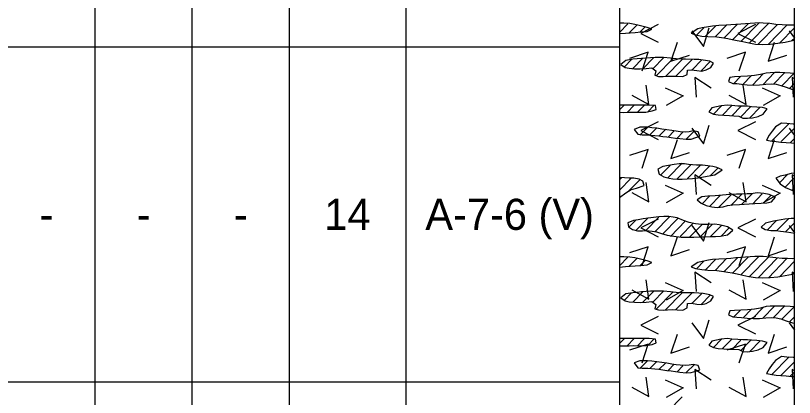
# Model space of a CAD drawing. Extents: x -0.01 to 0.83, y -0.63 to 1.27.
# Drawn here: x 0.6664 to 0.8333, y 0.7859 to 0.8677 of the extents above; entities that cross this region are included whole.
import ezdxf

# ---------------------------------------------------------------- set-up
doc = ezdxf.new("R2010")
doc.units = 0

msp = doc.modelspace()

# ---------------------------------------------------------------- linework, layer by layer
for points in [[(0, 0), (0.83333, 0), (0.83333, 1.275), (0, 1.275)], [(0, 0), (0.83333, 0), (0.83333, 1.275), (0, 1.275)], [(0, 0), (0.83333, 0), (0.83333, 1.275), (0, 1.275)], [(0, 0), (0.83333, 0), (0.83333, 1.275), (0, 1.275)], [(0, 0), (0.83333, 0), (0.83333, 1.275), (0, 1.275)], [(0.79583, 0.86382), (0.79715, 0.86393), (0.79814, 0.86401), (0.79922, 0.86408), (0.80039, 0.86417), (0.80179, 0.86429), (0.80275, 0.8648), (0.80179, 0.86515), (0.80091, 0.86536), (0.80003, 0.86558), (0.79909, 0.86579), (0.79803, 0.86595), (0.79677, 0.86605), (0.79583, 0.86603)], [(0.82816, 0.86157), (0.82978, 0.86174), (0.83137, 0.862), (0.8329, 0.86231), (0.83333, 0.86241), (0.83333, 0.86565), (0.83295, 0.86562), (0.83188, 0.86564), (0.83071, 0.86569), (0.82938, 0.8658), (0.82807, 0.86597), (0.82662, 0.86608), (0.82576, 0.86609), (0.82484, 0.86606), (0.82387, 0.86601), (0.82286, 0.86594), (0.82182, 0.86586), (0.82077, 0.86578), (0.81973, 0.86569), (0.81872, 0.86562), (0.81715, 0.86552), (0.81579, 0.86543), (0.81491, 0.8653), (0.81357, 0.86502), (0.8126, 0.86481), (0.81121, 0.86389), (0.8121, 0.86353), (0.81345, 0.86328), (0.81479, 0.86319), (0.81668, 0.86309), (0.81818, 0.86289), (0.81905, 0.86274), (0.82, 0.86257), (0.82107, 0.86235), (0.82225, 0.8621), (0.82357, 0.86181), (0.82501, 0.86158), (0.82656, 0.86151)], [(0.79708, 0.85659), (0.79794, 0.85641), (0.79904, 0.8563), (0.80028, 0.85627), (0.80156, 0.85632), (0.80274, 0.85648), (0.80361, 0.85582), (0.80338, 0.85492), (0.80422, 0.85465), (0.80517, 0.85463), (0.80613, 0.85469), (0.8072, 0.85472), (0.80818, 0.85469), (0.80939, 0.85461), (0.81037, 0.85508), (0.81038, 0.85602), (0.8113, 0.85609), (0.81244, 0.8559), (0.81346, 0.85579), (0.81438, 0.85605), (0.81539, 0.85659), (0.81601, 0.8575), (0.81517, 0.85788), (0.81374, 0.85815), (0.81285, 0.85825), (0.81187, 0.8583), (0.81, 0.85831), (0.8091, 0.85832), (0.808, 0.8584), (0.80678, 0.85856), (0.8053, 0.85869), (0.80443, 0.8587), (0.80349, 0.85868), (0.80251, 0.85864), (0.80152, 0.85858), (0.80054, 0.8585), (0.79959, 0.85841), (0.7987, 0.85831), (0.79722, 0.85809), (0.79614, 0.85721)], [(0.83241, 0.85537), (0.83129, 0.85544), (0.83017, 0.85547), (0.8291, 0.85548), (0.82811, 0.85544), (0.82728, 0.85535), (0.82608, 0.85505), (0.82476, 0.85482), (0.8233, 0.85469), (0.82183, 0.85461), (0.82051, 0.85455), (0.81951, 0.85445), (0.81922, 0.85358), (0.82013, 0.85316), (0.82097, 0.85311), (0.822, 0.85301), (0.82318, 0.85288), (0.82448, 0.85279), (0.82584, 0.85282), (0.82719, 0.85298), (0.82836, 0.85305), (0.8294, 0.85297), (0.83043, 0.85274), (0.83156, 0.85235), (0.83291, 0.85186), (0.83333, 0.85178), (0.83333, 0.8553)], [(0.79583, 0.84696), (0.79676, 0.84695), (0.79792, 0.84697), (0.79882, 0.84701), (0.79992, 0.84697), (0.80151, 0.84701), (0.80282, 0.84727), (0.80367, 0.84759), (0.80354, 0.84842), (0.80216, 0.84851), (0.79583, 0.84851)], [(0.81822, 0.84632), (0.81944, 0.84626), (0.82033, 0.84622), (0.82145, 0.84615), (0.82229, 0.84573), (0.82324, 0.84569), (0.82438, 0.8458), (0.82555, 0.84608), (0.82662, 0.84659), (0.82749, 0.84769), (0.82651, 0.84799), (0.82524, 0.84809), (0.82413, 0.84815), (0.82324, 0.84826), (0.82226, 0.84828), (0.82121, 0.8483), (0.81995, 0.84839), (0.81902, 0.84851), (0.81761, 0.84837), (0.81566, 0.84793), (0.81496, 0.84709), (0.81598, 0.8466), (0.81695, 0.84642)], [(0.80066, 0.84216), (0.80188, 0.84215), (0.80339, 0.84202), (0.80423, 0.84193), (0.8051, 0.84182), (0.806, 0.8417), (0.80692, 0.84158), (0.80784, 0.84146), (0.80875, 0.84135), (0.81014, 0.84121), (0.81119, 0.84122), (0.81222, 0.84157), (0.81308, 0.84185), (0.81267, 0.84275), (0.8116, 0.843), (0.81075, 0.8428), (0.80989, 0.84272), (0.80885, 0.8428), (0.80799, 0.84291), (0.80703, 0.84306), (0.806, 0.84322), (0.80492, 0.84339), (0.80384, 0.84354), (0.8028, 0.84367), (0.80182, 0.84377), (0.8002, 0.84378), (0.79901, 0.8433), (0.79974, 0.84226)], [(0.83305, 0.84446), (0.83171, 0.84457), (0.83054, 0.84467), (0.82925, 0.84385), (0.82857, 0.84294), (0.82792, 0.84205), (0.82735, 0.84103), (0.82858, 0.8408), (0.82945, 0.8407), (0.83045, 0.8406), (0.83155, 0.84051), (0.83272, 0.84041), (0.83333, 0.84036), (0.83333, 0.84445)], [(0.81233, 0.83565), (0.81063, 0.83577), (0.80977, 0.83591), (0.8086, 0.83591), (0.80755, 0.83577), (0.80632, 0.83557), (0.80513, 0.83533), (0.80403, 0.83481), (0.80436, 0.83374), (0.80536, 0.83318), (0.80647, 0.83288), (0.8073, 0.83273), (0.80824, 0.83265), (0.80926, 0.83264), (0.81035, 0.83269), (0.81149, 0.8328), (0.81267, 0.83294), (0.81386, 0.83313), (0.81506, 0.83334), (0.81625, 0.83357), (0.81783, 0.83466), (0.81673, 0.83515), (0.81585, 0.83536), (0.8148, 0.83551), (0.81361, 0.83562)], [(0.83265, 0.83384), (0.83136, 0.83353), (0.83028, 0.83326), (0.82934, 0.83286), (0.83026, 0.83166), (0.83142, 0.8309), (0.83279, 0.83032), (0.83333, 0.83022), (0.83333, 0.83393)], [(0.79583, 0.82874), (0.79719, 0.82973), (0.79831, 0.83044), (0.79951, 0.83071), (0.80111, 0.83131), (0.80086, 0.83219), (0.80002, 0.83267), (0.79889, 0.83286), (0.79791, 0.83289), (0.79694, 0.83295), (0.79583, 0.83303)], [(0.82537, 0.82969), (0.82408, 0.82954), (0.82319, 0.82948), (0.82214, 0.82946), (0.82091, 0.82942), (0.81947, 0.82933), (0.81792, 0.82921), (0.81632, 0.82909), (0.81475, 0.82899), (0.81348, 0.82889), (0.81247, 0.82825), (0.81337, 0.82749), (0.81444, 0.82699), (0.81561, 0.8267), (0.81675, 0.8266), (0.81807, 0.82671), (0.81896, 0.82698), (0.82003, 0.82713), (0.82157, 0.82725), (0.82253, 0.82731), (0.82362, 0.82737), (0.82483, 0.82743), (0.82618, 0.82749), (0.82745, 0.8276), (0.82842, 0.82778), (0.82927, 0.82883), (0.82791, 0.82935), (0.82679, 0.82955)], [(0.79885, 0.82378), (0.79763, 0.82332), (0.79773, 0.82242), (0.79859, 0.8219), (0.7997, 0.8216), (0.80074, 0.82161), (0.80165, 0.82163), (0.80281, 0.82154), (0.80377, 0.82134), (0.80486, 0.82099), (0.80606, 0.82069), (0.80751, 0.82042), (0.80905, 0.82023), (0.81052, 0.8202), (0.81177, 0.82026), (0.81289, 0.8203), (0.81408, 0.82033), (0.81553, 0.82037), (0.81642, 0.8204), (0.81745, 0.82043), (0.81897, 0.8207), (0.82011, 0.82174), (0.81896, 0.82241), (0.8181, 0.82268), (0.81717, 0.82287), (0.81626, 0.82298), (0.81479, 0.82292), (0.81343, 0.82292), (0.8121, 0.82307), (0.8108, 0.82337), (0.80953, 0.82383), (0.8082, 0.82438), (0.80736, 0.82454), (0.8064, 0.82462), (0.80536, 0.82462), (0.80427, 0.82456), (0.80314, 0.82445), (0.80201, 0.8243), (0.8009, 0.82414), (0.79984, 0.82396)], [(0.83263, 0.82423), (0.83126, 0.82409), (0.82969, 0.82382), (0.82883, 0.82365), (0.82712, 0.82324), (0.82623, 0.82237), (0.82708, 0.82188), (0.82831, 0.82169), (0.82941, 0.82163), (0.83033, 0.82154), (0.83165, 0.82135), (0.83253, 0.82121), (0.83333, 0.82107), (0.83333, 0.82422)], [(0.79583, 0.81382), (0.79715, 0.81393), (0.79814, 0.81401), (0.79922, 0.81408), (0.80039, 0.81417), (0.80179, 0.81429), (0.80275, 0.8148), (0.80179, 0.81515), (0.80091, 0.81536), (0.80003, 0.81558), (0.79909, 0.81579), (0.79803, 0.81595), (0.79677, 0.81605), (0.79583, 0.81603)], [(0.82816, 0.81157), (0.82978, 0.81174), (0.83137, 0.812), (0.8329, 0.81231), (0.83333, 0.81241), (0.83333, 0.81565), (0.83295, 0.81562), (0.83188, 0.81564), (0.83071, 0.81569), (0.82938, 0.8158), (0.82807, 0.81597), (0.82662, 0.81608), (0.82576, 0.81609), (0.82484, 0.81606), (0.82387, 0.81601), (0.82286, 0.81594), (0.82182, 0.81586), (0.82077, 0.81578), (0.81973, 0.81569), (0.81872, 0.81562), (0.81715, 0.81552), (0.81579, 0.81543), (0.81491, 0.8153), (0.81357, 0.81502), (0.8126, 0.81481), (0.81121, 0.81389), (0.8121, 0.81353), (0.81345, 0.81328), (0.81479, 0.81319), (0.81668, 0.81309), (0.81818, 0.81289), (0.81905, 0.81274), (0.82, 0.81257), (0.82107, 0.81235), (0.82225, 0.8121), (0.82357, 0.81181), (0.82501, 0.81158), (0.82656, 0.81151)], [(0.79708, 0.80659), (0.79794, 0.80641), (0.79904, 0.8063), (0.80028, 0.80627), (0.80156, 0.80632), (0.80274, 0.80648), (0.80361, 0.80582), (0.80338, 0.80492), (0.80422, 0.80465), (0.80517, 0.80463), (0.80613, 0.80469), (0.8072, 0.80472), (0.80818, 0.80469), (0.80939, 0.80461), (0.81037, 0.80508), (0.81038, 0.80602), (0.8113, 0.80609), (0.81244, 0.8059), (0.81346, 0.80579), (0.81438, 0.80605), (0.81539, 0.80659), (0.81601, 0.8075), (0.81517, 0.80788), (0.81374, 0.80815), (0.81285, 0.80825), (0.81187, 0.8083), (0.81, 0.80831), (0.8091, 0.80832), (0.808, 0.8084), (0.80678, 0.80856), (0.8053, 0.80869), (0.80443, 0.8087), (0.80349, 0.80868), (0.80251, 0.80864), (0.80152, 0.80858), (0.80054, 0.8085), (0.79959, 0.80841), (0.7987, 0.80831), (0.79722, 0.80809), (0.79614, 0.80721)], [(0.83241, 0.80537), (0.83129, 0.80544), (0.83017, 0.80548), (0.8291, 0.80548), (0.82811, 0.80544), (0.82728, 0.80535), (0.82608, 0.80505), (0.82476, 0.80482), (0.8233, 0.80469), (0.82183, 0.80461), (0.82051, 0.80455), (0.81951, 0.80445), (0.81922, 0.80358), (0.82013, 0.80316), (0.82097, 0.80311), (0.822, 0.80301), (0.82318, 0.80288), (0.82448, 0.80279), (0.82584, 0.80282), (0.82719, 0.80298), (0.82836, 0.80305), (0.8294, 0.80297), (0.83043, 0.80274), (0.83156, 0.80235), (0.83291, 0.80186), (0.83333, 0.80178), (0.83333, 0.8053)], [(0.79583, 0.79696), (0.79676, 0.79695), (0.79792, 0.79697), (0.79882, 0.79701), (0.79992, 0.79697), (0.80151, 0.79701), (0.80282, 0.79727), (0.80367, 0.79759), (0.80354, 0.79842), (0.80216, 0.79851), (0.79583, 0.79851)], [(0.81822, 0.79632), (0.81944, 0.79626), (0.82033, 0.79622), (0.82145, 0.79615), (0.82229, 0.79574), (0.82324, 0.79569), (0.82438, 0.7958), (0.82555, 0.79608), (0.82662, 0.79659), (0.82749, 0.79769), (0.82651, 0.79799), (0.82524, 0.79809), (0.82413, 0.79815), (0.82324, 0.79826), (0.82226, 0.79828), (0.82121, 0.7983), (0.81995, 0.79839), (0.81902, 0.79851), (0.81761, 0.79837), (0.81566, 0.79793), (0.81496, 0.79709), (0.81598, 0.7966), (0.81695, 0.79642)], [(0.80066, 0.79216), (0.80188, 0.79215), (0.80339, 0.79202), (0.80423, 0.79193), (0.8051, 0.79182), (0.806, 0.7917), (0.80692, 0.79158), (0.80784, 0.79146), (0.80875, 0.79135), (0.81014, 0.79121), (0.81119, 0.79122), (0.81222, 0.79157), (0.81308, 0.79185), (0.81267, 0.79275), (0.8116, 0.793), (0.81075, 0.7928), (0.80989, 0.79272), (0.80885, 0.7928), (0.80799, 0.79291), (0.80703, 0.79306), (0.806, 0.79322), (0.80492, 0.79339), (0.80384, 0.79354), (0.8028, 0.79367), (0.80182, 0.79377), (0.8002, 0.79378), (0.79901, 0.7933), (0.79974, 0.79226)], [(0.83305, 0.79446), (0.83171, 0.79457), (0.83054, 0.79467), (0.82925, 0.79385), (0.82857, 0.79294), (0.82792, 0.79205), (0.82735, 0.79103), (0.82858, 0.7908), (0.82945, 0.7907), (0.83045, 0.7906), (0.83155, 0.79051), (0.83272, 0.79041), (0.83333, 0.79036), (0.83333, 0.79445)]]:
    msp.add_lwpolyline(points, close=True)
for points in [[(0.725, 1.22083), (0.725, -0.62183)], [(0.75, 1.22083), (0.75, -0.62183)], [(0.75, 1.22083), (0.75, -0.62183)], [(0.79583, 1.22083), (0.79583, -0.62183)], [(0.68333, 1.20833), (0.68333, -0.62183)], [(0.70417, 1.20833), (0.70417, -0.62183)], [(0.725, 1.20833), (0.725, -0.62183)], [(0.83333, -0.62183), (0.83333, 1.13843)], [(0.79765, 0.86594), (0.79583, 0.86407)], [(0.7996, 0.86572), (0.79786, 0.86394)], [(0.8013, 0.86524), (0.80027, 0.86419)], [(0.80412, 0.86575), (0.80038, 0.86387), (0.80412, 0.862)], [(0.81134, 0.86441), (0.81384, 0.86103), (0.81503, 0.86503)], [(0.81392, 0.86508), (0.81235, 0.86348)], [(0.8143, 0.86326), (0.8165, 0.86551)], [(0.8164, 0.86319), (0.81879, 0.86564)], [(0.81829, 0.86291), (0.82114, 0.86584)], [(0.82004, 0.86249), (0.82346, 0.866)], [(0.82496, 0.86575), (0.82121, 0.86387), (0.82496, 0.862)], [(0.82569, 0.86608), (0.82184, 0.86213)], [(0.82775, 0.86598), (0.8237, 0.86183)], [(0.82964, 0.8657), (0.82557, 0.86152)], [(0.83173, 0.86563), (0.82774, 0.86154)], [(0.83333, 0.86506), (0.83012, 0.86176)], [(0.83217, 0.86441), (0.83333, 0.86284)], [(0.80818, 0.86191), (0.80687, 0.85791), (0.81087, 0.85923)], [(0.82901, 0.86191), (0.8277, 0.85791), (0.8317, 0.85923)], [(0.83281, 0.86231), (0.83333, 0.86284)], [(0.6625, 0.861), (0.68333, 0.861)], [(0.68333, 0.861), (0.70417, 0.861)], [(0.70417, 0.861), (0.725, 0.861)], [(0.725, 0.861), (0.75, 0.861)], [(0.75, 0.861), (0.79583, 0.861)], [(0.79844, 0.85828), (0.79691, 0.85671)], [(0.80069, 0.85583), (0.802, 0.85983), (0.798, 0.85852)], [(0.79871, 0.85634), (0.80085, 0.85853)], [(0.80083, 0.85629), (0.80311, 0.85863)], [(0.80534, 0.85871), (0.80299, 0.85629)], [(0.80367, 0.85478), (0.80732, 0.85852)], [(0.80571, 0.85466), (0.80924, 0.85828)], [(0.81142, 0.85829), (0.80785, 0.85464)], [(0.81141, 0.85607), (0.81348, 0.85819)], [(0.82152, 0.85583), (0.82284, 0.85983), (0.81884, 0.85852)], [(0.81528, 0.85783), (0.81331, 0.85581)], [(0.82433, 0.8528), (0.82666, 0.85519)], [(0.82909, 0.85548), (0.82656, 0.85288)], [(0.82885, 0.85301), (0.83122, 0.85544)], [(0.83325, 0.85531), (0.83065, 0.85265)], [(0.81551, 0.85211), (0.81201, 0.85442), (0.81226, 0.85023)], [(0.82035, 0.85315), (0.82176, 0.8546)], [(0.82233, 0.85298), (0.82408, 0.85476)], [(0.83333, 0.85318), (0.83227, 0.85209)], [(0.83333, 0.8541), (0.83284, 0.85442), (0.83309, 0.85023)], [(0.79847, 0.85063), (0.80215, 0.84863), (0.80153, 0.85275)], [(0.80562, 0.85217), (0.80946, 0.85049), (0.80581, 0.84843)], [(0.8193, 0.85063), (0.82299, 0.84863), (0.82236, 0.85275)], [(0.82645, 0.85217), (0.83029, 0.85049), (0.82664, 0.84843)], [(0.79583, 0.84748), (0.79681, 0.84848)], [(0.79898, 0.8485), (0.79747, 0.84695)], [(0.80116, 0.84851), (0.79959, 0.84691)], [(0.80328, 0.84847), (0.80188, 0.84704)], [(0.8177, 0.84837), (0.81596, 0.84659)], [(0.81988, 0.84839), (0.81785, 0.84631)], [(0.82185, 0.8482), (0.81997, 0.84627)], [(0.824, 0.84819), (0.82178, 0.84591)], [(0.82601, 0.84803), (0.82378, 0.84575)], [(0.80412, 0.84491), (0.80038, 0.84304), (0.80412, 0.84116)], [(0.82496, 0.84491), (0.82121, 0.84304), (0.82496, 0.84116)], [(0.80188, 0.84381), (0.8002, 0.84209)], [(0.8038, 0.84357), (0.80237, 0.84211)], [(0.80575, 0.84335), (0.80429, 0.84186)], [(0.81134, 0.84357), (0.81384, 0.8402), (0.81503, 0.8442)], [(0.83217, 0.84459), (0.82844, 0.84077)], [(0.83333, 0.84357), (0.83052, 0.84069)], [(0.83217, 0.84357), (0.83333, 0.84201)], [(0.80758, 0.84302), (0.80627, 0.84167)], [(0.80941, 0.84269), (0.80816, 0.8414)], [(0.81188, 0.843), (0.81016, 0.84124)], [(0.80818, 0.84108), (0.80687, 0.83708), (0.81087, 0.83839)], [(0.82901, 0.84108), (0.8277, 0.83708), (0.8317, 0.83839)], [(0.83333, 0.84136), (0.83245, 0.84045)], [(0.80069, 0.835), (0.802, 0.839), (0.798, 0.83769)], [(0.82152, 0.835), (0.82284, 0.839), (0.81884, 0.83769)], [(0.80465, 0.83354), (0.80667, 0.83561)], [(0.80626, 0.83297), (0.80928, 0.83607)], [(0.80809, 0.83264), (0.81111, 0.83573)], [(0.81041, 0.8328), (0.81318, 0.83563)], [(0.81264, 0.83288), (0.81518, 0.83548)], [(0.81536, 0.83345), (0.81699, 0.83511)], [(0.81551, 0.83128), (0.81201, 0.83359), (0.81226, 0.8294)], [(0.8301, 0.83187), (0.83184, 0.83366)], [(0.83333, 0.83327), (0.83284, 0.83359), (0.83309, 0.8294)], [(0.7963, 0.83299), (0.79583, 0.83251)], [(0.79834, 0.83286), (0.79583, 0.83029)], [(0.79786, 0.83016), (0.80023, 0.83259)], [(0.79847, 0.82979), (0.80215, 0.82779), (0.80153, 0.83192)], [(0.8193, 0.82979), (0.82299, 0.82779), (0.82236, 0.83192)], [(0.83131, 0.8309), (0.83333, 0.83298)], [(0.80562, 0.83134), (0.80946, 0.82965), (0.80581, 0.82759)], [(0.82645, 0.83134), (0.83029, 0.82965), (0.82664, 0.82759)], [(0.83285, 0.83027), (0.83333, 0.83076)], [(0.81519, 0.82906), (0.81354, 0.82736)], [(0.81514, 0.8268), (0.81748, 0.82919)], [(0.81709, 0.82658), (0.81974, 0.8293)], [(0.8197, 0.82703), (0.82203, 0.82943)], [(0.82202, 0.8272), (0.8243, 0.82954)], [(0.82431, 0.82733), (0.82644, 0.82952)], [(0.82663, 0.8275), (0.82834, 0.82925)], [(0.79938, 0.82391), (0.79786, 0.82236)], [(0.79933, 0.82165), (0.80195, 0.82434)], [(0.80412, 0.82408), (0.80038, 0.8222), (0.80412, 0.82033)], [(0.80142, 0.82158), (0.8043, 0.82453)], [(0.80653, 0.82461), (0.8034, 0.8214)], [(0.80506, 0.82089), (0.8084, 0.82431)], [(0.80997, 0.82371), (0.80675, 0.8204)], [(0.81164, 0.8232), (0.80884, 0.82034)], [(0.81134, 0.82274), (0.81384, 0.81936), (0.81503, 0.82336)], [(0.82496, 0.82408), (0.82121, 0.8222), (0.82496, 0.82033)], [(0.82751, 0.82176), (0.82945, 0.82375)], [(0.83203, 0.82417), (0.82949, 0.82157)], [(0.83138, 0.8213), (0.83333, 0.8233)], [(0.81353, 0.82293), (0.81094, 0.82027)], [(0.81303, 0.82021), (0.81579, 0.82303)], [(0.81534, 0.82036), (0.81768, 0.82276)], [(0.8176, 0.82047), (0.81934, 0.82225)], [(0.83217, 0.82274), (0.83333, 0.82118)], [(0.80818, 0.82025), (0.80687, 0.81625), (0.81087, 0.81756)], [(0.82901, 0.82025), (0.8277, 0.81625), (0.8317, 0.81756)], [(0.83333, 0.82108), (0.83333, 0.82109)], [(0.80069, 0.81417), (0.802, 0.81817), (0.798, 0.81686)], [(0.82152, 0.81417), (0.82284, 0.81817), (0.81884, 0.81686)], [(0.79765, 0.81594), (0.79583, 0.81407)], [(0.7996, 0.81572), (0.79786, 0.81394)], [(0.8013, 0.81524), (0.80027, 0.81419)], [(0.81392, 0.81508), (0.81235, 0.81348)], [(0.8143, 0.81326), (0.8165, 0.81551)], [(0.8164, 0.81319), (0.81879, 0.81564)], [(0.81829, 0.81291), (0.82114, 0.81584)], [(0.82004, 0.81249), (0.82346, 0.816)], [(0.82569, 0.81608), (0.82184, 0.81213)], [(0.82775, 0.81598), (0.8237, 0.81183)], [(0.82964, 0.8157), (0.82557, 0.81152)], [(0.83173, 0.81563), (0.82774, 0.81154)], [(0.83333, 0.81506), (0.83012, 0.81176)], [(0.81551, 0.81044), (0.81201, 0.81275), (0.81226, 0.80857)], [(0.83281, 0.81231), (0.83333, 0.81284)], [(0.83333, 0.81243), (0.83284, 0.81275), (0.83309, 0.80857)], [(0.79847, 0.80896), (0.80215, 0.80696), (0.80153, 0.81108)], [(0.80562, 0.8105), (0.80946, 0.80882), (0.80581, 0.80676)], [(0.8193, 0.80896), (0.82299, 0.80696), (0.82236, 0.81108)], [(0.82645, 0.8105), (0.83029, 0.80882), (0.82664, 0.80676)], [(0.79844, 0.80828), (0.79691, 0.80671)], [(0.79871, 0.80634), (0.80085, 0.80853)], [(0.80083, 0.80629), (0.80311, 0.80863)], [(0.80534, 0.80871), (0.80299, 0.80629)], [(0.80367, 0.80478), (0.80732, 0.80852)], [(0.80571, 0.80466), (0.80924, 0.80828)], [(0.81142, 0.80829), (0.80785, 0.80464)], [(0.81141, 0.80607), (0.81348, 0.80819)], [(0.81528, 0.80783), (0.81331, 0.80581)], [(0.82233, 0.80298), (0.82408, 0.80476)], [(0.82433, 0.8028), (0.82666, 0.80519)], [(0.82909, 0.80548), (0.82656, 0.80289)], [(0.82885, 0.80301), (0.83122, 0.80544)], [(0.83325, 0.80531), (0.83065, 0.80265)], [(0.80412, 0.80325), (0.80038, 0.80137), (0.80412, 0.7995)], [(0.82035, 0.80315), (0.82176, 0.8046)], [(0.82496, 0.80325), (0.82121, 0.80137), (0.82496, 0.7995)], [(0.83333, 0.80318), (0.83227, 0.80209)], [(0.81134, 0.80191), (0.81384, 0.79853), (0.81503, 0.80253)], [(0.83217, 0.80191), (0.83333, 0.80034)], [(0.79583, 0.79748), (0.79681, 0.79848)], [(0.79898, 0.7985), (0.79747, 0.79695)], [(0.80116, 0.79852), (0.79959, 0.79691)], [(0.80328, 0.79847), (0.80188, 0.79704)], [(0.80818, 0.79941), (0.80687, 0.79541), (0.81087, 0.79673)], [(0.8177, 0.79837), (0.81596, 0.79659)], [(0.81988, 0.79839), (0.81785, 0.79631)], [(0.82185, 0.7982), (0.81997, 0.79627)], [(0.824, 0.79819), (0.82178, 0.79591)], [(0.82901, 0.79941), (0.8277, 0.79541), (0.8317, 0.79673)], [(0.80069, 0.79333), (0.802, 0.79733), (0.798, 0.79602)], [(0.82152, 0.79333), (0.82284, 0.79733), (0.81884, 0.79602)], [(0.82601, 0.79803), (0.82378, 0.79575)], [(0.80188, 0.79381), (0.8002, 0.79209)], [(0.8038, 0.79357), (0.80237, 0.79211)], [(0.80575, 0.79335), (0.80429, 0.79186)], [(0.83217, 0.79459), (0.82844, 0.79077)], [(0.83333, 0.79357), (0.83052, 0.79069)], [(0.80758, 0.79302), (0.80627, 0.79167)], [(0.80941, 0.79269), (0.80816, 0.7914)], [(0.81188, 0.793), (0.81016, 0.79124)], [(0.81551, 0.78961), (0.81201, 0.79192), (0.81226, 0.78773)], [(0.83333, 0.7916), (0.83284, 0.79192), (0.83309, 0.78773)], [(0.79847, 0.78813), (0.80215, 0.78613), (0.80153, 0.79025)], [(0.8193, 0.78813), (0.82299, 0.78613), (0.82236, 0.79025)], [(0.83333, 0.79136), (0.83245, 0.79045)], [(0.6625, 0.78925), (0.68333, 0.78925)], [(0.68333, 0.78925), (0.70417, 0.78925)], [(0.70417, 0.78925), (0.725, 0.78925)], [(0.725, 0.78925), (0.75, 0.78925)], [(0.75, 0.78925), (0.79583, 0.78925)], [(0.80562, 0.78967), (0.80946, 0.78799), (0.80581, 0.78593)], [(0.82645, 0.78967), (0.83029, 0.78799), (0.82664, 0.78593)], [(0.80626, 0.78297), (0.80928, 0.78607)]]:
    msp.add_lwpolyline(points)

# ---------------------------------------------------------------- texts
for s, height, p in [('14', 0.006667, (0.73255, 0.82179)), ('A-7-6 (V)', 0.006667, (0.7542, 0.82179)), ('-', 0.00667, (0.67151, 0.82179)), ('-', 0.00667, (0.69234, 0.82179)), ('-', 0.00667, (0.71318, 0.82179))]:
    msp.add_text(s, height=height).set_placement(p)

doc.saveas('drawing.dxf')
